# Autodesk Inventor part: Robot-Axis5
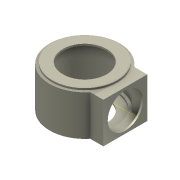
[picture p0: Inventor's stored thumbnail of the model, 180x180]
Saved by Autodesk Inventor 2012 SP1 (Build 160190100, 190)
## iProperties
Shininess: 21.0
Length Units: 11269
Angle Units: 11279
Time Units: 11290
Mass Units: 11283
Length Display Precision: 3
Angle Display Precision: 2
Created: 2001-08
Part Number: Robot-Axis5
Document SubType Name: ﾓﾃﾞﾘﾝｸﾞ
Designer: Administrator
Density: 1 g/cm^3
Material: Default
Density: 0.0
Volumn: 0.0
Area: 0.0
PropertySet Name: Model Information
Control State: 0
Master: False
Checked Out: False
Author: Administrator
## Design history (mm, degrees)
sketch "ｽｹｯﾁ1"
  geometry: C1 r 40 at (0, 0)
  constraints: 1 centre point
  dimensions: "d0" = 80 diameter of C1
extrude "押し出し1" new body sketch "ｽｹｯﾁ1" taper "d2" = 0 deg
sketch "ｽｹｯﾁ2"
  geometry: C1 r 40 at (0, 0) reference; C2 r 37 at (0, 0)
  constraints: 1 centre point
  dimensions: "d3" = 3 radial gap between concentric circles of C1 C2
extrude "押し出し2" join sketch "ｽｹｯﾁ2" distance "d4" = 2; taper "d5" = 0 deg
node "作業平面1"
sketch "ｽｹｯﾁ3"
  geometry: L1 (-37, -25)-(37, -25) reference; L2 (40, -23)-(-40, -23) reference; L3 (-25, 23)-(25, 23); L4 (25, 23)-(25, -23); L5 (25, -23)-(-25, -23); L6 (-25, -23)-(-25, 23); L7 (-25, 0)-(25, 0); L8 (0, 23)-(0, -23); L9 (0, -23)-(0, 24.715)
  constraints: 14 end point, 6 midpoint, 2 collinear, 2 parallel, 2 perpendicular, 1 horizontal, 1 point on line
  dimensions: "d6" = 50 distance of L3.start L3.end; "d7" = 46 distance of L5.end L3.start; "d8" = 25 distance between parallel lines of L6 L8
extrude "押し出し3" join sketch "ｽｹｯﾁ3" distance "d9" = 46.2; taper "d10" = 0 deg
node "作業軸1"
workaxis "Work Axis2"
  workplane "Work Plane2"
  workplane "Work Plane3"
shell "Shell1" dims "d20" = 2
sketch "Sketch7"
  geometry: C1 r 37 at (0, 0) reference
hole "Hole1" sketch "Sketch7" at (0, 0) diameter "d21" = 50; stored, may be unused: countersink angle "d25" = 82 deg, drill point angle "d27" = 118 deg; dims "d22" = 6, "d23" = 4, "d24" = 2, "d26" = 8
sketch "Sketch8"
  geometry: 1 further point
hole "Hole2" sketch "Sketch8" at (0, 0) diameter "d28" = 40; stored, may be unused: countersink angle "d32" = 82 deg, drill point angle "d34" = 118 deg; dims "d29" = 6, "d30" = 4, "d31" = 2, "d33" = 2
body "Solid1"
mirror "Mirror1"
sketch "Sketch4"
  geometry: 1 further point
